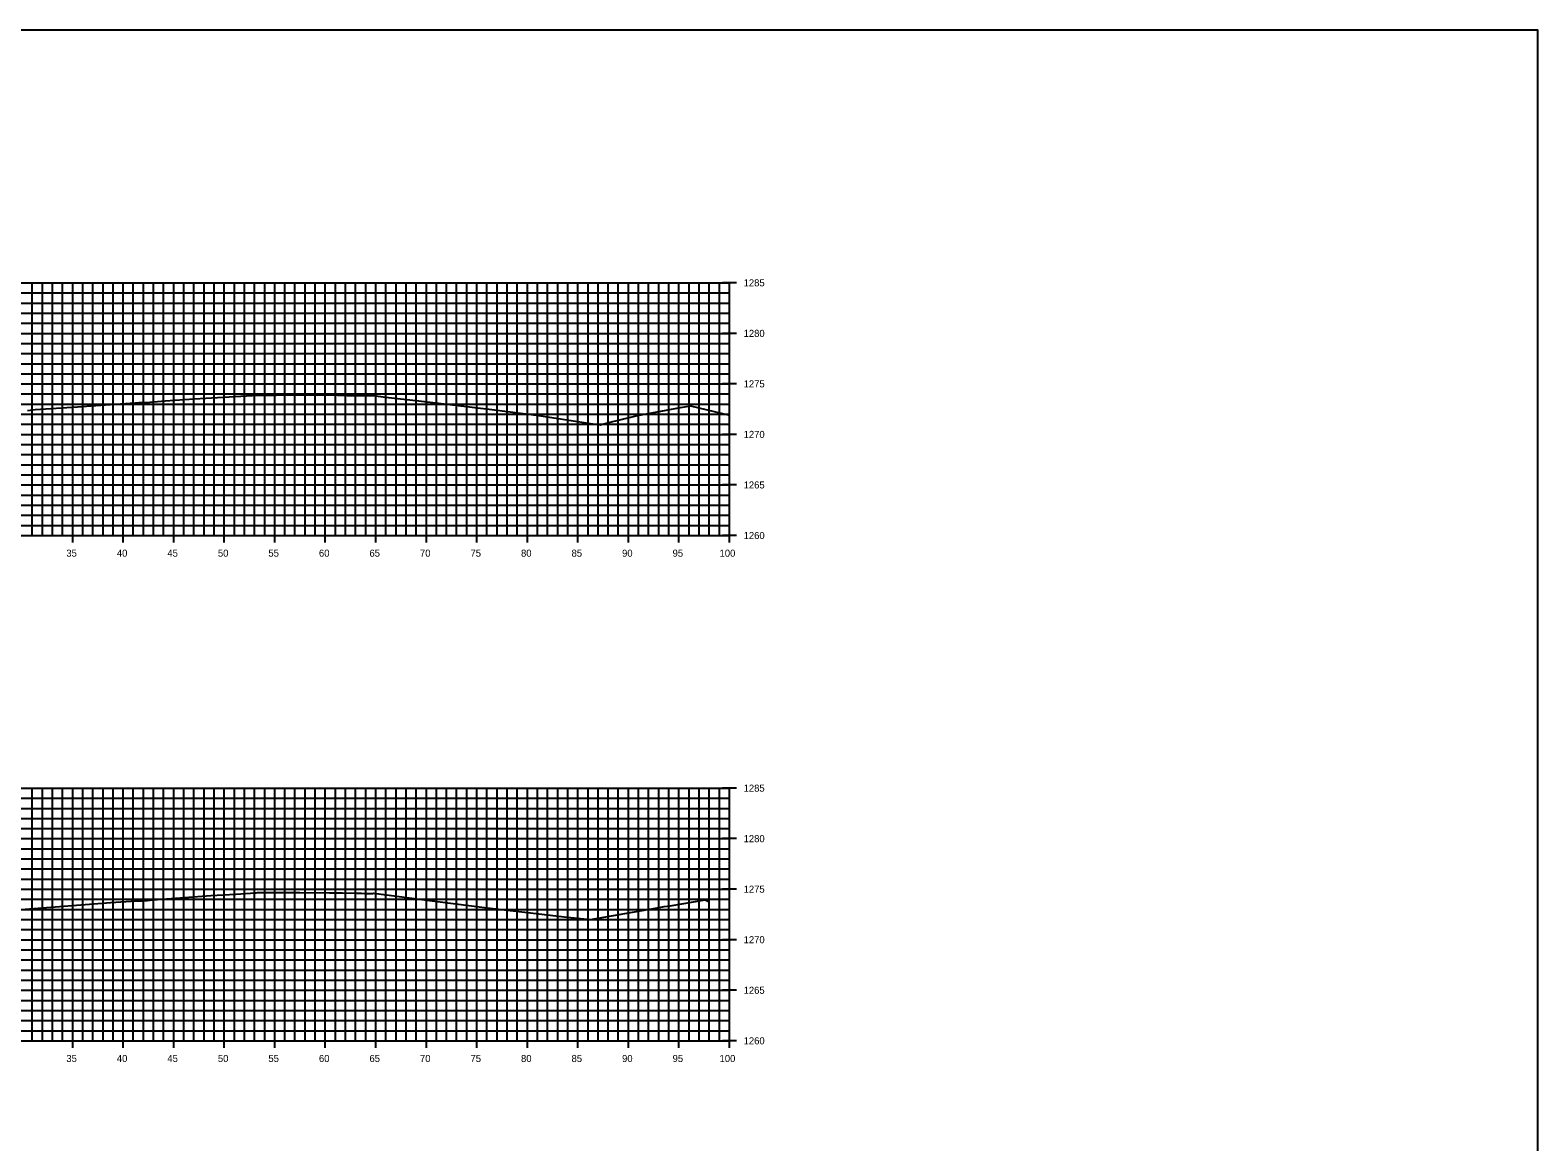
# Model space of a CAD drawing. Extents: x 674939 to 678919, y 750652 to 765176.
# Drawn here: x 678769.3 to 678918.5, y 756782.6 to 756892.6 of the extents above; entities that cross this region are included whole.
import ezdxf

# ---------------------------------------------------------------- set-up
doc = ezdxf.new("R2010")
doc.units = 0
for name, color, linetype in [('R_Axis', 7, 'Continuous'), ('R_Axis Annot', 7, 'Continuous'), ('R_Exist Surface', 7, 'Continuous'), ('R_Grid', 7, 'Continuous'), ('R_No Plot', 7, 'Continuous')]:
    doc.layers.add(name, color=color, linetype=linetype)

msp = doc.modelspace()

# ---------------------------------------------------------------- linework, layer by layer
at = {"layer": 'R_Axis'}
for p, q in [((678839.23, 756867.55), (678837.83, 756867.55)), ((678838.53, 756842.55), (678838.53, 756867.55)), ((678839.23, 756862.55), (678837.83, 756862.55)), ((678839.23, 756857.55), (678837.83, 756857.55)), ((678839.23, 756852.55), (678837.83, 756852.55)), ((678839.23, 756847.55), (678837.83, 756847.55)), ((678773.53, 756841.85), (678773.53, 756843.25)), ((678778.53, 756841.85), (678778.53, 756843.25)), ((678783.53, 756841.85), (678783.53, 756843.25)), ((678788.53, 756841.85), (678788.53, 756843.25)), ((678793.53, 756841.85), (678793.53, 756843.25)), ((678798.53, 756841.85), (678798.53, 756843.25)), ((678803.53, 756841.85), (678803.53, 756843.25)), ((678808.53, 756841.85), (678808.53, 756843.25)), ((678813.53, 756841.85), (678813.53, 756843.25)), ((678818.53, 756841.85), (678818.53, 756843.25)), ((678823.53, 756841.85), (678823.53, 756843.25)), ((678828.53, 756841.85), (678828.53, 756843.25)), ((678833.53, 756841.85), (678833.53, 756843.25)), ((678838.53, 756841.85), (678838.53, 756843.25)), ((678638.53, 756842.55), (678838.53, 756842.55)), ((678839.23, 756842.55), (678837.83, 756842.55)), ((678839.23, 756817.55), (678837.83, 756817.55)), ((678838.53, 756792.55), (678838.53, 756817.55)), ((678839.23, 756812.55), (678837.83, 756812.55)), ((678839.23, 756807.55), (678837.83, 756807.55)), ((678839.23, 756802.55), (678837.83, 756802.55)), ((678839.23, 756797.55), (678837.83, 756797.55)), ((678638.53, 756792.55), (678838.53, 756792.55)), ((678773.53, 756791.85), (678773.53, 756793.25)), ((678778.53, 756791.85), (678778.53, 756793.25)), ((678783.53, 756791.85), (678783.53, 756793.25)), ((678788.53, 756791.85), (678788.53, 756793.25)), ((678793.53, 756791.85), (678793.53, 756793.25)), ((678798.53, 756791.85), (678798.53, 756793.25)), ((678803.53, 756791.85), (678803.53, 756793.25)), ((678808.53, 756791.85), (678808.53, 756793.25)), ((678813.53, 756791.85), (678813.53, 756793.25)), ((678818.53, 756791.85), (678818.53, 756793.25)), ((678823.53, 756791.85), (678823.53, 756793.25)), ((678828.53, 756791.85), (678828.53, 756793.25)), ((678833.53, 756791.85), (678833.53, 756793.25)), ((678839.23, 756792.55), (678837.83, 756792.55)), ((678838.53, 756791.85), (678838.53, 756793.25))]:
    msp.add_line(p, q, dxfattribs=at)
at = {"layer": 'R_Exist Surface'}
for points in [[(678769.07, 756854.93), (678769.83, 756855), (678774, 756855.29), (678775.82, 756855.42), (678779.71, 756855.68), (678780.06, 756855.7), (678780.66, 756855.71), (678780.81, 756855.71), (678781.16, 756855.74), (678782.67, 756855.87), (678785.54, 756856.06), (678786.71, 756856.14), (678790.73, 756856.37), (678791.91, 756856.43), (678791.99, 756856.44), (678792.06, 756856.44), (678793.28, 756856.45), (678793.66, 756856.45), (678794.27, 756856.47), (678795.45, 756856.47), (678799.73, 756856.43), (678800.71, 756856.41), (678803.22, 756856.39), (678803.29, 756856.4), (678804.49, 756856.25), (678807.8, 756855.88), (678815, 756855.02), (678819.67, 756854.42), (678824.77, 756853.64), (678825.72, 756853.51), (678826.46, 756853.7), (678829.43, 756854.41), (678833.68, 756855.2), (678834.67, 756855.37), (678838.53, 756854.45)], [(678768.81, 756805.59), (678771.79, 756805.82), (678774.32, 756806), (678777.31, 756806.22), (678779.82, 756806.39), (678780.14, 756806.39), (678780.51, 756806.39), (678780.94, 756806.44), (678781.5, 756806.5), (678784.61, 756806.73), (678787.21, 756806.92), (678789.67, 756807.07), (678791.62, 756807.2), (678791.7, 756807.2), (678791.82, 756807.21), (678792.65, 756807.22), (678793.73, 756807.21), (678796.01, 756807.21), (678798.95, 756807.2), (678800.23, 756807.18), (678801.64, 756807.15), (678802.1, 756807.15), (678802.42, 756807.14), (678802.64, 756807.12), (678802.91, 756807.11), (678803.19, 756807.13), (678803.3, 756807.15), (678805.6, 756806.85), (678807.81, 756806.56), (678814.55, 756805.71), (678818.83, 756805.21), (678822.16, 756804.8), (678824.77, 756804.55), (678831.22, 756805.67), (678832.05, 756805.83), (678832.65, 756805.91), (678836.12, 756806.5), (678836.47, 756806.33)]]:
    msp.add_lwpolyline(points, dxfattribs=at)
at = {"layer": 'R_Grid'}
for p, q in [((678638.53, 756867.55), (678838.53, 756867.55)), ((678769.53, 756842.55), (678769.53, 756867.55)), ((678770.53, 756842.55), (678770.53, 756867.55)), ((678771.53, 756842.55), (678771.53, 756867.55)), ((678772.53, 756842.55), (678772.53, 756867.55)), ((678773.53, 756842.55), (678773.53, 756867.55)), ((678774.53, 756842.55), (678774.53, 756867.55)), ((678775.53, 756842.55), (678775.53, 756867.55)), ((678776.53, 756842.55), (678776.53, 756867.55)), ((678777.53, 756842.55), (678777.53, 756867.55)), ((678778.53, 756842.55), (678778.53, 756867.55)), ((678779.53, 756842.55), (678779.53, 756867.55)), ((678780.53, 756842.55), (678780.53, 756867.55)), ((678781.53, 756842.55), (678781.53, 756867.55)), ((678782.53, 756842.55), (678782.53, 756867.55)), ((678783.53, 756842.55), (678783.53, 756867.55)), ((678784.53, 756842.55), (678784.53, 756867.55)), ((678785.53, 756842.55), (678785.53, 756867.55)), ((678786.53, 756842.55), (678786.53, 756867.55)), ((678787.53, 756842.55), (678787.53, 756867.55)), ((678788.53, 756842.55), (678788.53, 756867.55)), ((678789.53, 756842.55), (678789.53, 756867.55)), ((678790.53, 756842.55), (678790.53, 756867.55)), ((678791.53, 756842.55), (678791.53, 756867.55)), ((678792.53, 756842.55), (678792.53, 756867.55)), ((678793.53, 756842.55), (678793.53, 756867.55)), ((678794.53, 756842.55), (678794.53, 756867.55)), ((678795.53, 756842.55), (678795.53, 756867.55)), ((678796.53, 756842.55), (678796.53, 756867.55)), ((678797.53, 756842.55), (678797.53, 756867.55)), ((678798.53, 756842.55), (678798.53, 756867.55)), ((678799.53, 756842.55), (678799.53, 756867.55)), ((678800.53, 756842.55), (678800.53, 756867.55)), ((678801.53, 756842.55), (678801.53, 756867.55)), ((678802.53, 756842.55), (678802.53, 756867.55)), ((678803.53, 756842.55), (678803.53, 756867.55)), ((678804.53, 756842.55), (678804.53, 756867.55)), ((678805.53, 756842.55), (678805.53, 756867.55)), ((678806.53, 756842.55), (678806.53, 756867.55)), ((678807.53, 756842.55), (678807.53, 756867.55)), ((678808.53, 756842.55), (678808.53, 756867.55)), ((678809.53, 756842.55), (678809.53, 756867.55)), ((678810.53, 756842.55), (678810.53, 756867.55)), ((678811.53, 756842.55), (678811.53, 756867.55)), ((678812.53, 756842.55), (678812.53, 756867.55)), ((678813.53, 756842.55), (678813.53, 756867.55)), ((678814.53, 756842.55), (678814.53, 756867.55)), ((678815.53, 756842.55), (678815.53, 756867.55)), ((678816.53, 756842.55), (678816.53, 756867.55)), ((678817.53, 756842.55), (678817.53, 756867.55)), ((678818.53, 756842.55), (678818.53, 756867.55)), ((678819.53, 756842.55), (678819.53, 756867.55)), ((678820.53, 756842.55), (678820.53, 756867.55)), ((678821.53, 756842.55), (678821.53, 756867.55)), ((678822.53, 756842.55), (678822.53, 756867.55)), ((678823.53, 756842.55), (678823.53, 756867.55)), ((678824.53, 756842.55), (678824.53, 756867.55)), ((678825.53, 756842.55), (678825.53, 756867.55)), ((678826.53, 756842.55), (678826.53, 756867.55)), ((678827.53, 756842.55), (678827.53, 756867.55)), ((678828.53, 756842.55), (678828.53, 756867.55)), ((678829.53, 756842.55), (678829.53, 756867.55)), ((678830.53, 756842.55), (678830.53, 756867.55)), ((678831.53, 756842.55), (678831.53, 756867.55)), ((678832.53, 756842.55), (678832.53, 756867.55)), ((678833.53, 756842.55), (678833.53, 756867.55)), ((678834.53, 756842.55), (678834.53, 756867.55)), ((678835.53, 756842.55), (678835.53, 756867.55)), ((678836.53, 756842.55), (678836.53, 756867.55)), ((678837.53, 756842.55), (678837.53, 756867.55)), ((678838.53, 756842.55), (678838.53, 756867.55)), ((678638.53, 756866.55), (678838.53, 756866.55)), ((678638.53, 756865.55), (678838.53, 756865.55)), ((678638.53, 756864.55), (678838.53, 756864.55)), ((678638.53, 756863.55), (678838.53, 756863.55)), ((678638.53, 756862.55), (678838.53, 756862.55)), ((678638.53, 756861.55), (678838.53, 756861.55)), ((678638.53, 756860.55), (678838.53, 756860.55)), ((678638.53, 756859.55), (678838.53, 756859.55)), ((678638.53, 756858.55), (678838.53, 756858.55)), ((678638.53, 756857.55), (678838.53, 756857.55)), ((678638.53, 756856.55), (678838.53, 756856.55)), ((678638.53, 756855.55), (678838.53, 756855.55)), ((678638.53, 756854.55), (678838.53, 756854.55)), ((678638.53, 756853.55), (678838.53, 756853.55)), ((678638.53, 756852.55), (678838.53, 756852.55)), ((678638.53, 756851.55), (678838.53, 756851.55)), ((678638.53, 756850.55), (678838.53, 756850.55)), ((678638.53, 756849.55), (678838.53, 756849.55)), ((678638.53, 756848.55), (678838.53, 756848.55)), ((678638.53, 756847.55), (678838.53, 756847.55)), ((678638.53, 756846.55), (678838.53, 756846.55)), ((678638.53, 756845.55), (678838.53, 756845.55)), ((678638.53, 756844.55), (678838.53, 756844.55)), ((678638.53, 756843.55), (678838.53, 756843.55)), ((678638.53, 756842.55), (678838.53, 756842.55)), ((678638.53, 756817.55), (678838.53, 756817.55)), ((678638.53, 756816.55), (678838.53, 756816.55)), ((678769.53, 756792.55), (678769.53, 756817.55)), ((678770.53, 756792.55), (678770.53, 756817.55)), ((678771.53, 756792.55), (678771.53, 756817.55)), ((678772.53, 756792.55), (678772.53, 756817.55)), ((678773.53, 756792.55), (678773.53, 756817.55)), ((678774.53, 756792.55), (678774.53, 756817.55)), ((678775.53, 756792.55), (678775.53, 756817.55)), ((678776.53, 756792.55), (678776.53, 756817.55)), ((678777.53, 756792.55), (678777.53, 756817.55)), ((678778.53, 756792.55), (678778.53, 756817.55)), ((678779.53, 756792.55), (678779.53, 756817.55)), ((678780.53, 756792.55), (678780.53, 756817.55)), ((678781.53, 756792.55), (678781.53, 756817.55)), ((678782.53, 756792.55), (678782.53, 756817.55)), ((678783.53, 756792.55), (678783.53, 756817.55)), ((678784.53, 756792.55), (678784.53, 756817.55)), ((678785.53, 756792.55), (678785.53, 756817.55)), ((678786.53, 756792.55), (678786.53, 756817.55)), ((678787.53, 756792.55), (678787.53, 756817.55)), ((678788.53, 756792.55), (678788.53, 756817.55)), ((678789.53, 756792.55), (678789.53, 756817.55)), ((678790.53, 756792.55), (678790.53, 756817.55)), ((678791.53, 756792.55), (678791.53, 756817.55)), ((678792.53, 756792.55), (678792.53, 756817.55)), ((678793.53, 756792.55), (678793.53, 756817.55)), ((678794.53, 756792.55), (678794.53, 756817.55)), ((678795.53, 756792.55), (678795.53, 756817.55)), ((678796.53, 756792.55), (678796.53, 756817.55)), ((678797.53, 756792.55), (678797.53, 756817.55)), ((678798.53, 756792.55), (678798.53, 756817.55)), ((678799.53, 756792.55), (678799.53, 756817.55)), ((678800.53, 756792.55), (678800.53, 756817.55)), ((678801.53, 756792.55), (678801.53, 756817.55)), ((678802.53, 756792.55), (678802.53, 756817.55)), ((678803.53, 756792.55), (678803.53, 756817.55)), ((678804.53, 756792.55), (678804.53, 756817.55)), ((678805.53, 756792.55), (678805.53, 756817.55)), ((678806.53, 756792.55), (678806.53, 756817.55)), ((678807.53, 756792.55), (678807.53, 756817.55)), ((678808.53, 756792.55), (678808.53, 756817.55)), ((678809.53, 756792.55), (678809.53, 756817.55)), ((678810.53, 756792.55), (678810.53, 756817.55)), ((678811.53, 756792.55), (678811.53, 756817.55)), ((678812.53, 756792.55), (678812.53, 756817.55)), ((678813.53, 756792.55), (678813.53, 756817.55)), ((678814.53, 756792.55), (678814.53, 756817.55)), ((678815.53, 756792.55), (678815.53, 756817.55)), ((678816.53, 756792.55), (678816.53, 756817.55)), ((678817.53, 756792.55), (678817.53, 756817.55)), ((678818.53, 756792.55), (678818.53, 756817.55)), ((678819.53, 756792.55), (678819.53, 756817.55)), ((678820.53, 756792.55), (678820.53, 756817.55)), ((678821.53, 756792.55), (678821.53, 756817.55)), ((678822.53, 756792.55), (678822.53, 756817.55)), ((678823.53, 756792.55), (678823.53, 756817.55)), ((678824.53, 756792.55), (678824.53, 756817.55)), ((678825.53, 756792.55), (678825.53, 756817.55)), ((678826.53, 756792.55), (678826.53, 756817.55)), ((678827.53, 756792.55), (678827.53, 756817.55)), ((678828.53, 756792.55), (678828.53, 756817.55)), ((678829.53, 756792.55), (678829.53, 756817.55)), ((678830.53, 756792.55), (678830.53, 756817.55)), ((678831.53, 756792.55), (678831.53, 756817.55)), ((678832.53, 756792.55), (678832.53, 756817.55)), ((678833.53, 756792.55), (678833.53, 756817.55)), ((678834.53, 756792.55), (678834.53, 756817.55)), ((678835.53, 756792.55), (678835.53, 756817.55)), ((678836.53, 756792.55), (678836.53, 756817.55)), ((678837.53, 756792.55), (678837.53, 756817.55)), ((678838.53, 756792.55), (678838.53, 756817.55)), ((678638.53, 756815.55), (678838.53, 756815.55)), ((678638.53, 756814.55), (678838.53, 756814.55)), ((678638.53, 756813.55), (678838.53, 756813.55)), ((678638.53, 756812.55), (678838.53, 756812.55)), ((678638.53, 756811.55), (678838.53, 756811.55)), ((678638.53, 756810.55), (678838.53, 756810.55)), ((678638.53, 756809.55), (678838.53, 756809.55)), ((678638.53, 756808.55), (678838.53, 756808.55)), ((678638.53, 756807.55), (678838.53, 756807.55)), ((678638.53, 756806.55), (678838.53, 756806.55)), ((678638.53, 756805.55), (678838.53, 756805.55)), ((678638.53, 756804.55), (678838.53, 756804.55)), ((678638.53, 756803.55), (678838.53, 756803.55)), ((678638.53, 756802.55), (678838.53, 756802.55)), ((678638.53, 756801.55), (678838.53, 756801.55)), ((678638.53, 756800.55), (678838.53, 756800.55)), ((678638.53, 756799.55), (678838.53, 756799.55)), ((678638.53, 756798.55), (678838.53, 756798.55)), ((678638.53, 756797.55), (678838.53, 756797.55)), ((678638.53, 756796.55), (678838.53, 756796.55)), ((678638.53, 756795.55), (678838.53, 756795.55)), ((678638.53, 756794.55), (678838.53, 756794.55)), ((678638.53, 756793.55), (678838.53, 756793.55)), ((678638.53, 756792.55), (678838.53, 756792.55))]:
    msp.add_line(p, q, dxfattribs=at)
at = {"layer": 'R_No Plot'}
msp.add_lwpolyline([(678578.53, 756672.55), (678918.53, 756672.55), (678918.53, 756892.55), (678578.53, 756892.55)], close=True, dxfattribs=at)

# ---------------------------------------------------------------- texts
at = {"layer": 'R_Axis Annot'}
for s, p in [('1285', (678839.93, 756867.2)), ('1280', (678839.93, 756862.2)), ('1275', (678839.93, 756857.2)), ('1270', (678839.93, 756852.2)), ('1265', (678839.93, 756847.2)), ('1260', (678839.93, 756842.2)), ('35', (678772.9, 756840.45)), ('40', (678777.9, 756840.45)), ('45', (678782.9, 756840.45)), ('50', (678787.9, 756840.45)), ('55', (678792.9, 756840.45)), ('60', (678797.9, 756840.45)), ('65', (678802.9, 756840.45)), ('70', (678807.9, 756840.45)), ('75', (678812.9, 756840.45)), ('80', (678817.9, 756840.45)), ('85', (678822.9, 756840.45)), ('90', (678827.9, 756840.45)), ('95', (678832.9, 756840.45)), ('100', (678837.55, 756840.45)), ('1285', (678839.93, 756817.2)), ('1280', (678839.93, 756812.2)), ('1275', (678839.93, 756807.2)), ('1270', (678839.93, 756802.2)), ('1265', (678839.93, 756797.2)), ('1260', (678839.93, 756792.2)), ('35', (678772.9, 756790.45)), ('40', (678777.9, 756790.45)), ('45', (678782.9, 756790.45)), ('50', (678787.9, 756790.45)), ('55', (678792.9, 756790.45)), ('60', (678797.9, 756790.45)), ('65', (678802.9, 756790.45)), ('70', (678807.9, 756790.45)), ('75', (678812.9, 756790.45)), ('80', (678817.9, 756790.45)), ('85', (678822.9, 756790.45)), ('90', (678827.9, 756790.45)), ('95', (678832.9, 756790.45)), ('100', (678837.55, 756790.45))]:
    msp.add_text(s, height=0.7, dxfattribs=at).set_placement(p)

doc.saveas('drawing.dxf')
